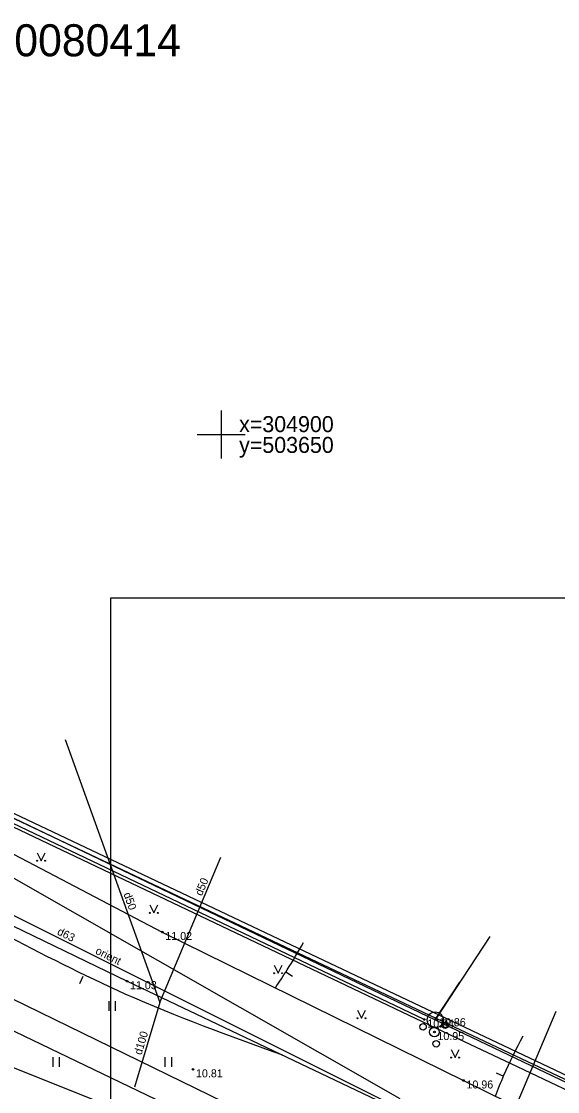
# Model space of a CAD drawing. Extents: x 503353 to 504004, y 304662 to 305049.
# Drawn here: x 503637.5 to 503671, y 304859 to 304925.8 of the extents above; entities that cross this region are included whole.
import ezdxf

# ---------------------------------------------------------------- set-up
doc = ezdxf.new("R2010")
doc.units = 0
for name, color, linetype in [('24', 7, 'Continuous'), ('59', 7, 'Continuous'), ('APGR_ELEM_####_####_#', 7, 'Continuous'), ('APGR_SARK_####_####_#', 7, 'Continuous'), ('CELI_CMAL_####_####_#', 7, 'Continuous'), ('DREN_VADP_####_####_#', 7, 'Continuous'), ('DREN_VADP_####_TKST_#', 7, 'Continuous'), ('DREN_VADP_KLKT_####_#', 7, 'Continuous'), ('DREN_VADP_KLKT_TKST_#', 7, 'Continuous'), ('ELEK_VADP_ZSPR_####_#', 7, 'Continuous'), ('ELEK_VADP_ZSPR_####_I', 7, 'Continuous'), ('GAZE_VADP_VSP2_####_I', 7, 'Continuous'), ('GEOD_ELEM_####_####_#', 7, 'Continuous'), ('GEOD_KORD_####_TKST_#', 7, 'Continuous'), ('NORB_ZOGS_ZSTP_####_#', 7, 'Continuous'), ('RAMI_PLAN_####_TKST_#', 7, 'Continuous'), ('RAMI_UZMR_####_####_#', 7, 'Continuous'), ('RELJ_AATZ_####_TKST_#', 7, 'Continuous'), ('RELJ_ELEM_####_####_#', 7, 'Continuous'), ('RELJ_HORZ_PAMT_####_#', 7, 'Continuous'), ('TERT_ELEM_####_####_#', 7, 'Continuous'), ('TERT_KRND_####_####_#', 7, 'Continuous'), ('UDTK_VADP_UDEN_####_#', 7, 'Continuous'), ('UDTK_VADP_UDEN_TKST_#', 7, 'Continuous')]:
    doc.layers.add(name, color=color, linetype=linetype)

msp = doc.modelspace()

# ---------------------------------------------------------------- linework, layer by layer
at = {"layer": '24'}
for p, q in [((503597.271, 304884.111), (503674.34, 304846.523)), ((503666.772, 304868.653), (503663.371, 304863.436))]:
    msp.add_line(p, q, dxfattribs=at)
at = {"layer": 'APGR_ELEM_####_####_#'}
msp.add_circle((503663.37, 304863.44), 0.5, dxfattribs=at)
at = {"layer": 'APGR_SARK_####_####_#'}
for p, q in [((503608.368, 304889.745), (503663.371, 304863.436)), ((503596.04, 304882.339), (503658.194, 304852.61)), ((503663.371, 304863.436), (503697.707, 304847.023))]:
    msp.add_line(p, q, dxfattribs=at)
at = {"layer": 'CELI_CMAL_####_####_#'}
for points in [[(503613.299, 304880.595), (503629.802, 304872.768), (503644.109, 304865.856), (503663.603, 304856.591), (503684.211, 304846.236), (503716.62, 304830.397), (503750.714, 304813.753), (503759.331, 304809.396), (503770.944, 304803.486), (503794.752, 304792.108), (503812.819, 304782.96), (503836.268, 304772.627), (503857.062, 304763.632), (503889.596, 304749.28)], [(503632.385, 304876.195), (503646.316, 304868.926), (503665.133, 304859.653), (503687.416, 304848.681)]]:
    msp.add_lwpolyline(points, dxfattribs=at)
at = {"layer": 'DREN_VADP_####_####_#'}
for p, q in [((503640.254, 304880.96), (503646.151, 304864.521)), ((503646.151, 304864.521), (503649.976, 304873.592))]:
    msp.add_line(p, q, dxfattribs=at)
msp.add_lwpolyline([(503663.798, 304847.118), (503670.933, 304863.987)], dxfattribs=at)
at = {"layer": 'DREN_VADP_KLKT_####_#'}
msp.add_lwpolyline([(503646.151, 304864.521), (503644.585, 304859.239)], dxfattribs=at)
at = {"layer": 'ELEK_VADP_ZSPR_####_#'}
for points in [[(503664.432, 304862.445), (503668.093, 304860.71)], [(503668.093, 304860.71), (503685.3, 304852.554)]]:
    msp.add_lwpolyline(points, dxfattribs=at)
at = {"layer": 'ELEK_VADP_ZSPR_####_I'}
msp.add_lwpolyline([(503602.234, 304892.027), (503656.944, 304865.995), (503664.699, 304862.319)], dxfattribs=at)
at = {"layer": 'GAZE_VADP_VSP2_####_I'}
msp.add_line((503623.026, 304880.274), (503661.15, 304858.537), dxfattribs=at)
at = {"layer": 'GEOD_ELEM_####_####_#'}
for p, q in [((503650, 304901.5), (503650, 304900)), ((503650, 304901.5), (503650, 304900)), ((503648.5, 304900), (503650, 304900)), ((503648.5, 304900), (503650, 304900)), ((503650, 304900), (503650, 304898.5)), ((503650, 304900), (503651.5, 304900)), ((503650, 304900), (503650, 304898.5)), ((503650, 304900), (503651.5, 304900))]:
    msp.add_line(p, q, dxfattribs=at)
at = {"layer": 'NORB_ZOGS_ZSTP_####_#'}
for points in [[(503633.163, 304877.85), (503663.416, 304863.542), (503689.353, 304851.279)], [(503664.89, 304865.79), (503663.416, 304863.542)]]:
    msp.add_lwpolyline(points, dxfattribs=at)
at = {"layer": 'RAMI_PLAN_####_TKST_#'}
msp.add_lwpolyline([(503840.281, 304747.19), (503643.096, 304747.19), (503643.096, 304889.794), (503840.281, 304889.794)], close=True, dxfattribs=at)
at = {"layer": 'RAMI_UZMR_####_####_#'}
for points in [[(503407.219, 305023.925), (503368.776, 305020.183), (503379.431, 304977.462), (503383.452, 304957.421), (503396.867, 304960.598), (503416.959, 304959.032), (503433.698, 304951.36), (503608.791, 304871.751), (503642.724, 304858.177), (503694.651, 304834.724), (503842.283, 304765.867)], [(503825.923, 304784.828), (503697.433, 304847.709), (503608.51, 304889.842), (503606.524, 304897.202), (503679.244, 304999.942), (503684.897, 305009.76), (503666.777, 305017.939), (503656.134, 304996.39), (503644.103, 304987.6), (503600.987, 304924.263), (503587.985, 304916.668), (503422.237, 304989.372), (503408.615, 305023.495), (503368.776, 305020.183)]]:
    msp.add_lwpolyline(points, dxfattribs=at)
at = {"layer": 'RELJ_ELEM_####_####_#'}
for centre in [(503646.316, 304868.926), (503644.109, 304865.856), (503662.686, 304863.462), (503663.416, 304863.542), (503663.319, 304862.677), (503648.233, 304860.348), (503665.133, 304859.653)]:
    msp.add_circle(centre, 0.05, dxfattribs=at)
at = {"layer": 'RELJ_HORZ_PAMT_####_#'}
for p, q in [((503654.447, 304866.152), (503654.026, 304866.422)), ((503641.162, 304865.711), (503641.369, 304866.167)), ((503667.179, 304860.128), (503667.637, 304859.928))]:
    msp.add_line(p, q, dxfattribs=at)
for points in [[(503653.856, 304861.224), (503644.002, 304865.053), (503628.506, 304872.58), (503611.965, 304878.986), (503602.441, 304884.188), (503591.366, 304889.404), (503588.291, 304891.572), (503604.352, 304917.909), (503624.778, 304937.692)], [(503653.381, 304865.444), (503654.119, 304866.568), (503655.13, 304868.261)], [(503667.131, 304858.669), (503667.662, 304859.985), (503668.854, 304862.443)]]:
    msp.add_spline(points, degree=3, dxfattribs=at)
at = {"layer": 'TERT_ELEM_####_####_#'}
for p, q in [((503638.495, 304873.881), (503638.745, 304873.381)), ((503638.745, 304873.381), (503638.995, 304873.881)), ((503645.53, 304870.619), (503645.78, 304870.119)), ((503645.78, 304870.119), (503646.03, 304870.619)), ((503653.296, 304866.851), (503653.546, 304866.351)), ((503653.546, 304866.351), (503653.796, 304866.851)), ((503643, 304864), (503643, 304864.6)), ((503643.4, 304864), (503643.4, 304864.6)), ((503658.506, 304864.041), (503658.756, 304863.541)), ((503658.756, 304863.541), (503659.006, 304864.041)), ((503639.5, 304860.5), (503639.5, 304861.1)), ((503639.9, 304860.5), (503639.9, 304861.1)), ((503646.5, 304860.5), (503646.5, 304861.1)), ((503646.9, 304860.5), (503646.9, 304861.1)), ((503664.358, 304861.583), (503664.608, 304861.083)), ((503664.608, 304861.083), (503664.858, 304861.583))]:
    msp.add_line(p, q, dxfattribs=at)
for centre, radius in [((503638.495, 304873.38), 0.028), ((503638.995, 304873.38), 0.0263), ((503645.53, 304870.118), 0.028), ((503646.03, 304870.118), 0.0263), ((503653.296, 304866.351), 0.028), ((503653.796, 304866.351), 0.0263), ((503658.506, 304863.54), 0.028), ((503659.006, 304863.54), 0.0263), ((503662.605, 304863.001), 0.204), ((503663.319, 304862.677), 0.301), ((503663.98, 304863.102), 0.207), ((503663.422, 304861.949), 0.205), ((503664.358, 304861.083), 0.028), ((503664.858, 304861.083), 0.0263)]:
    msp.add_circle(centre, radius, dxfattribs=at)
at = {"layer": 'TERT_KRND_####_####_#'}
msp.add_lwpolyline([(503662.686, 304863.462), (503614.884, 304886.236)], dxfattribs=at)
at = {"layer": 'UDTK_VADP_UDEN_####_#'}
msp.add_lwpolyline([(503600.655, 304888.132), (503660.783, 304858.093)], dxfattribs=at)

# ---------------------------------------------------------------- texts
at = {"layer": '59'}
msp.add_text('80760080414', height=2, dxfattribs=at).set_placement((503631.115, 304923.624))
at = {"layer": 'DREN_VADP_####_TKST_#'}
for rotation, p in [(67.13715, (503648.782, 304871.147)), (289.73254, (503643.879, 304871.3))]:
    msp.add_text('d50', height=0.5, rotation=rotation, dxfattribs=at).set_placement(p)
at = {"layer": 'DREN_VADP_KLKT_TKST_#'}
msp.add_text('d100', height=0.5, rotation=73.48362, dxfattribs=at).set_placement((503645.014, 304861.214))
at = {"layer": 'GEOD_KORD_####_TKST_#'}
for s, p in [('   x=304900', (503650, 304900.15)), ('   y=503650', (503650, 304898.85))]:
    msp.add_text(s, height=1, dxfattribs=at).set_placement(p)
at = {"layer": 'RELJ_AATZ_####_TKST_#'}
for s, p in [(' 11.02', (503646.316, 304868.426)), (' 11.03', (503644.109, 304865.356)), (' 10.84', (503662.686, 304862.962)), (' 10.86', (503663.416, 304863.042)), (' 10.95', (503663.319, 304862.177)), (' 10.81', (503648.233, 304859.848)), (' 10.96', (503665.133, 304859.153))]:
    msp.add_text(s, height=0.5, dxfattribs=at).set_placement(p)
at = {"layer": 'UDTK_VADP_UDEN_TKST_#'}
for s, p in [('d63', (503639.7, 304868.794)), ('orient', (503642.088, 304867.592))]:
    msp.add_text(s, height=0.5, rotation=333.45407, dxfattribs=at).set_placement(p)

doc.saveas('drawing.dxf')
